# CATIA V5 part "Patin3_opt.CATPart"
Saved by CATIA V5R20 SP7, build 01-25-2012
Part number: Patin3
Bounding box of the stored display mesh (mm): x 0 to 15, y -52.866 to 5.998, z 16.032 to 116.944
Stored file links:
  J:\cmilovidofIAO\piece modifiée\Patin3_opt.CATPart
  J:\cmilovidofIAO\IAO optimisé\cmilovidof.CATProduct
  J:\cmilovidofIAO\IAO optimisé\Equerre7.CATPart
  J:\cmilovidofIAO\IAO optimisé\Patin3.CATPart
  J:\cmilovidofIAO\IAO optimisé\Patin2.CATPart
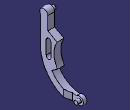
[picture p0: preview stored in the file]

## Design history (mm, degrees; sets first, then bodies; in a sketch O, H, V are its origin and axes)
External parameters (linked from other documents)
  External.diam_roue = 64 mm
  External.diam_roue.1 = 64 mm
Set1
  Plane1: linked copy from another document
  Line1 "Axe_Patin2Patin1": linked copy from another document
  Line2 "Axe_Equerre7Patin3": linked copy from another document
  Point1: linked copy from another document
  DatumCurve1: linked copy from another document
Body1 (main body)
  Sketch1 on Plane1, origin (5, 0, 0), H (0, 1, 0), V (0, 0, 1)
    arc A1 centre (0, 22) radius 6 from (-4.3493, 26.1332) to (-2.2168, 16.4245) cw
    line L1 (-26.8375, 50.5716) -> (-35.3014, 45.075)
    construction line L2 (0, 68) -> (-26.8375, 50.5716)
    arc A2 centre (-47, 111) radius 6 from (-51.6231, 107.1755) to (-41.0001, 110.9687) cw
    line L3 (-27.5084, 84.349) -> (-41.0001, 91.7955)
    axis line L4 (0, 68) -> (-26.9913, 82.8973)
    point P1 (0, 68)
    arc A3 centre (0, 68) radius 51.6231 from (-2.2168, 16.4245) to (-51.6231, 68) cw
    line L5 (-51.6231, 68) -> (-51.6231, 107.1755)
    point P2 (-51.6231, 107.1755)
    point P3 (-51.6231, 107.1755)
    point P4 (-51.6231, 68)
    point P5 (-51.6231, 68)
    point P6 (-35.3014, 45.075)
    point P7 (-35.3014, 45.075)
    point P8 (-4.3493, 26.1332)
    point P9 (-4.3493, 26.1332)
    construction line L6 (-41.0001, 110.9687) -> (-42.0613, 66.3896)
    construction arc A4 centre (0, 68) radius 42.0921 from (-4.3493, 26.1332) to (-42.0613, 66.3896) cw
    arc A5 centre (0, 68) radius 32 from (-26.8375, 50.5716) to (-27.5084, 84.349) cw
    line L7 (-41.0001, 110.9687) -> (-41.0001, 91.7955)
    arc A6 centre (0, 68) radius 42.0921 from (-4.3493, 26.1332) to (-35.3014, 45.075) cw
    reference projected point E1 (0, 22) from Line1
    reference projected point E2 (-47, 111) from Line2
    reference projected point E3 (0, 22) from Point1
    radius A1 = 6 {= External.diam_roue *6/64}
    angle L2 L4 = 61.8956
    radius A5 = 32 {= External.diam_roue *32/64}
    radius A2 = 6 {= 6*External.diam_roue /64}
    distance A6 A3 = 9.531 {= 9.531*External.diam_roue /64}
    distance P1 E3 = 46
    angle L1 V = 57
    distance L7 L5 = 10.623 {= 10.623*External.diam_roue /64}
    parallelism: L2 L1, L4 L3
    tangency: L5 A3
    vertical: L5 V
    coincidence: P3 P2, P5 P4, P7 P6, P9 P8, P1 V
    concentricity: A1 E1, A2 E2
  Pad1: profile Sketch1, direction (1, 0, 0), length 10
  Sketch2 on start face of Pad1, origin (5, 0, 0), H (0, -1, 0), V (0, 0, 1)
    circle A1 centre (47, 111) radius 3
    reference projected arc E1 centre (47, 111) radius 6 from (41.7867, 113.9701) to (49.3785, 116.5084) ccw from edge of DatumCurve1
    radius A1 = 3 {= 3*External.diam_roue /64}
    concentricity: E1 A1
  Pad2: profile Sketch2, direction (-1, 0, 0), length 5
  Sketch3 on end face of Pad1, origin (15, 0, 0), H (0, 1, 0), V (0, 0, 1)
    line L1 (10, 32) -> (-10, 32)
    line L2 (-10, 32) -> (-10, 12)
    line L3 (-10, 12) -> (10, 12)
    line L4 (10, 12) -> (10, 32)
    reference projected point E1 (0, 22) from Point1
    reference projected point E2 (0, 22) from Point1
    distance L2 L4 = 20
    distance L3 L1 = 20
    distance L4 E1 = 10
    distance E2 L1 = 10
    horizontal: L1 H, L3 H
    vertical: L2 V, L4 V
  Pocket1: profile Sketch3, direction (-1, 0, 0), length 5
  Sketch4 on end face of Pocket1, origin (10, 0, 0), H (0, 1, 0), V (0, 0, 1)
    circle A1 centre (0, 22) radius 3
    reference projected arc E1 centre (0, 22) radius 6 from (-2.2168, 16.4245) to (-4.3493, 26.1332) ccw from edge [face of Pad1 from Sketch1.A1 | end face of Pocket1]
    radius A1 = 3 {= 3*External.diam_roue /64}
    concentricity: A1 E1
  Pad3: profile Sketch4, direction (1, 0, 0), length 5
  Chamfer1: length 8.5, angle 30, on edge [end face of Pad1 | face of Pocket1 from Sketch3.L2]
  Sketch5 on end face of Pad1, origin (15, 0, 0), H (0, 1, 0), V (0, 0, 1)
    construction line L1 (-40, 80) -> (-40, 60)
    line L2 (-36.5, 80) -> (-36.5, 60)
    line L3 (-43.5, 60) -> (-43.5, 80)
    arc A1 centre (-40, 60) radius 3.5 from (-36.5, 60) to (-43.5, 60) cw
    arc A2 centre (-40, 80) radius 3.5 from (-43.5, 80) to (-36.5, 80) cw
    distance L1 L2 = 3.5
    tangency: A1 L2, A2 L2, A1 L3, A2 L3
  Pocket2: profile Sketch5, direction (-1, 0, 0), through (limit type 6)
